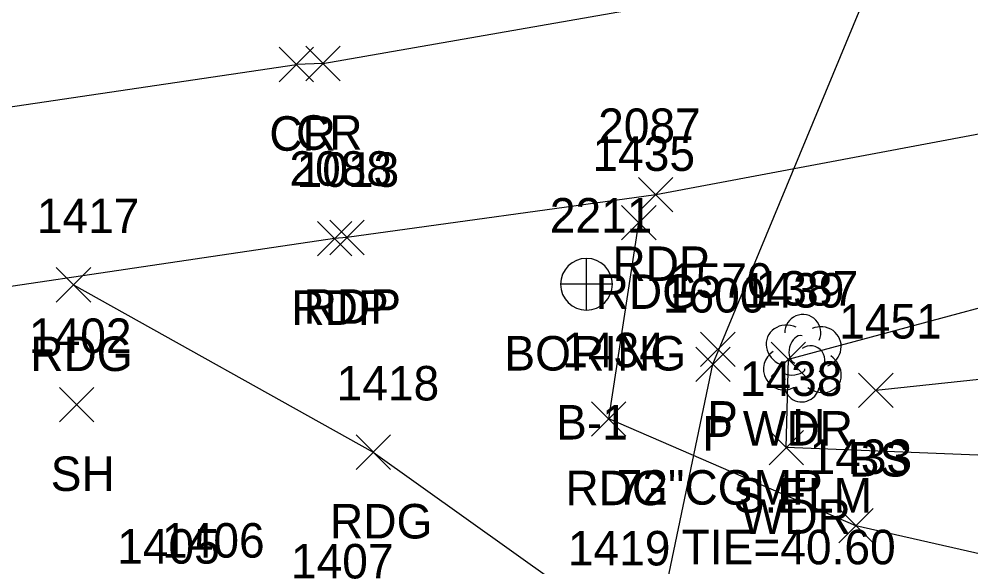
# Model space of a CAD drawing. Extents: x 1526508 to 1531550, y 369926 to 373082.
# Drawn here: x 1531020.1 to 1531075.3, y 370111.3 to 370143.1 of the extents above; entities that cross this region are included whole.
import ezdxf

# ---------------------------------------------------------------- set-up
doc = ezdxf.new("R2010")
doc.units = 0
for name, color, linetype in [('D_A', 7, 'Continuous'), ('D_C', 7, 'Continuous'), ('D_I', 7, 'Continuous'), ('D_TIC', 7, 'Continuous'), ('DCP', 7, 'Continuous'), ('G_A', 7, 'Continuous'), ('G_C', 7, 'Continuous'), ('G_I', 7, 'Continuous'), ('GA_P', 7, 'Continuous'), ('L_A', 7, 'Continuous'), ('L_C', 7, 'Continuous'), ('L_I', 7, 'Continuous'), ('L_TIC', 7, 'Continuous'), ('LAWA', 7, 'Continuous'), ('LELB', 7, 'Continuous'), ('LTD', 7, 'Continuous'), ('P_A', 7, 'Continuous'), ('P_I', 7, 'Continuous'), ('P_TIC', 7, 'Continuous'), ('PET', 7, 'Continuous'), ('PEU', 7, 'Continuous'), ('PRC', 7, 'Continuous')]:
    doc.layers.add(name, color=color, linetype=linetype)

msp = doc.modelspace()

# ---------------------------------------------------------------- linework, layer by layer
at = {"layer": 'D_TIC'}
for points in [[(1531059.668, 370122.959), (1531061.668, 370124.959)], [(1531061.668, 370122.959), (1531059.668, 370124.959)], [(1531059.382, 370122.096), (1531061.382, 370124.096)], [(1531061.382, 370122.096), (1531059.382, 370124.096)]]:
    msp.add_lwpolyline(points, dxfattribs=at)
at = {"layer": 'DCP'}
msp.add_lwpolyline([(1531055.491, 370099.698), (1531060.382, 370123.096), (1531085.607, 370183.89)], dxfattribs=at)
at = {"layer": 'GA_P'}
for p, q in [((1531053.045, 370127.735), (1531053.045, 370129.235)), ((1531053.045, 370127.735), (1531051.545, 370127.735)), ((1531054.545, 370127.735), (1531053.045, 370127.735)), ((1531053.045, 370126.235), (1531053.045, 370127.735))]:
    msp.add_line(p, q, dxfattribs=at)
for start, end in [(90, 180), (0, 90), (180, 270), (270, 0)]:
    msp.add_arc((1531053.045, 370127.735), 1.5, start, end, dxfattribs=at)
at = {"layer": 'L_TIC'}
for points in [[(1531063.755, 370122.384), (1531065.755, 370124.384)], [(1531065.755, 370122.384), (1531063.755, 370124.384)], [(1531068.826, 370120.59), (1531070.826, 370122.59)], [(1531070.826, 370120.59), (1531068.826, 370122.59)], [(1531022.481, 370119.754), (1531024.481, 370121.754)], [(1531024.481, 370119.754), (1531022.481, 370121.754)], [(1531063.636, 370117.264), (1531065.636, 370119.264)], [(1531065.636, 370117.264), (1531063.636, 370119.264)]]:
    msp.add_lwpolyline(points, dxfattribs=at)
at = {"layer": 'LAWA'}
msp.add_lwpolyline([(1531110.364, 370111.613), (1531088.81, 370117.303), (1531064.636, 370118.264), (1531064.755, 370123.384), (1531085.735, 370129.033), (1531112.085, 370135.206), (1531155.648, 370147.139), (1531210.22, 370163.604)], dxfattribs=at)
at = {"layer": 'LELB'}
msp.add_lwpolyline([(1531069.826, 370121.59), (1531102.347, 370125.05), (1531131.114, 370129.39)], dxfattribs=at)
at = {"layer": 'LTD'}
msp.add_line((1531065.548, 370123.502), (1531065.548, 370123.502), dxfattribs=at)
msp.add_line((1531065.548, 370123.502), (1531065.548, 370123.502), dxfattribs=at)
msp.add_arc((1531065.595, 370124.936), 1.047, 335.5272, 180.9563, dxfattribs=at)
for centre, major_axis, ratio, start_param, end_param in [((1531064.756, 370124.169), (1.21, -0.512), 0.895232, 1.570796, 4.712389), ((1531066.589, 370124.086), (-1.141, -0.483), 0.949671, 1.570796, 4.712389), ((1531065.339, 370123.96), (-0.208, -0.792), 0.645439, 3.141593, 6.283185), ((1531066.048, 370123.336), (-0.5, 0.667), 0.989748, 3.141593, 6.283185), ((1531064.465, 370122.794), (0.584, -1.042), 0.959034, 3.141593, 6.283185), ((1531066.548, 370122.669), (-1.09, 0.792), 0.841452, 1.570796, 4.712389), ((1531065.09, 370122.752), (-0.625, -0.083), 0.423636, 0, 3.141593), ((1531065.548, 370122.002), (0.265, 1.061), 0.942809, 1.570796, 4.712389)]:
    msp.add_ellipse(centre, major_axis=major_axis, ratio=ratio, start_param=start_param, end_param=end_param, dxfattribs=at)
at = {"layer": 'P_TIC'}
for points in [[(1531035.217, 370139.477), (1531037.217, 370141.477)], [(1531037.217, 370139.477), (1531035.217, 370141.477)], [(1531036.763, 370139.532), (1531038.763, 370141.532)], [(1531038.763, 370139.532), (1531036.763, 370141.532)], [(1531056.059, 370131.928), (1531058.059, 370133.928)], [(1531058.059, 370131.928), (1531056.059, 370133.928)], [(1531055.084, 370130.308), (1531057.084, 370132.308)], [(1531057.084, 370130.308), (1531055.084, 370132.308)], [(1531037.439, 370129.381), (1531039.439, 370131.381)], [(1531039.439, 370129.381), (1531037.439, 370131.381)], [(1531038.154, 370129.446), (1531040.154, 370131.446)], [(1531040.154, 370129.446), (1531038.154, 370131.446)], [(1531022.29, 370126.706), (1531024.29, 370128.706)], [(1531024.29, 370126.706), (1531022.29, 370128.706)], [(1531053.334, 370118.927), (1531055.334, 370120.927)], [(1531055.334, 370118.927), (1531053.334, 370120.927)], [(1531039.68, 370116.999), (1531041.68, 370118.999)], [(1531041.68, 370116.999), (1531039.68, 370118.999)], [(1531067.676, 370112.738), (1531069.676, 370114.738)], [(1531069.676, 370112.738), (1531067.676, 370114.738)]]:
    msp.add_lwpolyline(points, dxfattribs=at)
at = {"layer": 'PET'}
for points in [[(1531538.536, 370286.021), (1531506.284, 370274.482), (1531462.757, 370259.55), (1531429.61, 370248.076), (1531393.109, 370234.633), (1531350.619, 370219.916), (1531310.671, 370205.954), (1531271.31, 370192.301), (1531228.453, 370178.009), (1531188.403, 370165.276), (1531155.956, 370155.782), (1531116.2, 370145.37), (1531081.97, 370137.606), (1531057.059, 370132.928), (1531039.154, 370130.446)], [(1531038.439, 370130.381), (1531006.599, 370125.669), (1530965.469, 370120.559), (1530935.626, 370115.811), (1530906.909, 370106.244), (1530877.457, 370092.886), (1530855.502, 370080.74), (1530824.981, 370062.428), (1530800.479, 370048.152), (1530769.959, 370030.14), (1530741.096, 370012.789), (1530710.763, 369994.526), (1530684.029, 369978.659), (1530669.597, 369970.091)], [(1531039.154, 370130.446), (1531038.439, 370130.381)]]:
    msp.add_lwpolyline(points, dxfattribs=at)
at = {"layer": 'PEU'}
for points in [[(1531132.305, 370060.9), (1531128.071, 370080.387), (1531123.919, 370092.189), (1531113.282, 370102.83), (1531106.52, 370106.994), (1531097.458, 370108.784), (1531079.316, 370111.323), (1531068.676, 370113.738), (1531054.334, 370119.927), (1531056.084, 370131.308)], [(1531023.29, 370127.706), (1531040.68, 370117.999), (1531054.099, 370108.435), (1531069.601, 370103.939), (1531084.917, 370101.163), (1531104.196, 370096.573), (1531116.34, 370088.254), (1531119.549, 370080.003), (1531124.942, 370058.759)]]:
    msp.add_lwpolyline(points, dxfattribs=at)
at = {"layer": 'PRC'}
for points in [[(1531037.763, 370140.532), (1531081.386, 370148.168), (1531130.613, 370160.035), (1531176.301, 370172.813), (1531216.718, 370185.489), (1531265.367, 370201.607), (1531315.135, 370219.142), (1531364.467, 370236.544), (1531403.005, 370250.24), (1531441.257, 370263.858), (1531484.777, 370279.08), (1531519.825, 370291.48), (1531535.781, 370296.891)], [(1530664.429, 369978.533), (1530688.651, 369992.904), (1530715.759, 370008.787), (1530744.405, 370025.809), (1530774.386, 370044.325), (1530799.133, 370059.29), (1530828.468, 370076.59), (1530863.719, 370096.733), (1530899.644, 370113.889), (1530935.777, 370125.965), (1530974.766, 370132.269), (1531009.674, 370136.559), (1531036.217, 370140.477)], [(1531037.763, 370140.532), (1531036.217, 370140.477)]]:
    msp.add_lwpolyline(points, dxfattribs=at)

# ---------------------------------------------------------------- texts
at = {"layer": 'D_A'}
for p in [(1531060.045, 370118.959), (1531059.76, 370118.096)]:
    msp.add_text('P', height=2, dxfattribs=at).set_placement(p)
at = {"layer": 'D_C'}
msp.add_text('72"CGMP', height=2, dxfattribs=at).set_placement((1531054.801, 370114.959))
at = {"layer": 'D_I'}
for s, p in [('1570', (1531057.888, 370126.959)), ('1600', (1531057.477, 370126.096))]:
    msp.add_text(s, height=2, dxfattribs=at).set_placement(p)
at = {"layer": 'G_A'}
msp.add_text('BORING', height=2, dxfattribs=at).set_placement((1531048.282, 370122.735))
at = {"layer": 'G_C'}
msp.add_text('B-1', height=2, dxfattribs=at).set_placement((1531051.282, 370118.735))
at = {"layer": 'G_I'}
msp.add_text('2211', height=2, dxfattribs=at).set_placement((1531050.919, 370130.735))
at = {"layer": 'L_A'}
for s, p in [('WDR', (1531062.117, 370118.384)), ('H', (1531064.981, 370118.502)), ('BS', (1531068.267, 370116.59)), ('SH', (1531021.969, 370115.754)), ('WDR', (1531061.999, 370113.264))]:
    msp.add_text(s, height=2, dxfattribs=at).set_placement(p)
at = {"layer": 'L_C'}
for s, p in [('S.ELM', (1531061.579, 370114.502)), ('TIE=40.60', (1531058.564, 370111.502))]:
    msp.add_text(s, height=2, dxfattribs=at).set_placement(p)
at = {"layer": 'L_I'}
for s, p in [('1387', (1531062.855, 370126.502)), ('1439', (1531062.054, 370126.384)), ('1451', (1531067.7, 370124.59)), ('1402', (1531020.709, 370123.754)), ('1438', (1531061.943, 370121.264)), ('1406', (1531028.429, 370111.889)), ('1405', (1531025.826, 370111.539)), ('1407', (1531035.904, 370110.681))]:
    msp.add_text(s, height=2, dxfattribs=at).set_placement(p)
at = {"layer": 'P_A'}
for s, p in [('CR', (1531034.65, 370135.477)), ('CR', (1531036.196, 370135.532)), ('RDP', (1531054.548, 370127.928)), ('RDG', (1531053.572, 370126.308)), ('RDP', (1531036.642, 370125.446)), ('RDP', (1531035.928, 370125.381)), ('RDG', (1531020.779, 370122.706)), ('RDG', (1531051.823, 370114.927)), ('RDG', (1531038.168, 370112.999))]:
    msp.add_text(s, height=2, dxfattribs=at).set_placement(p)
at = {"layer": 'P_I'}
for s, p in [('2087', (1531053.721, 370135.928)), ('1435', (1531053.391, 370134.308)), ('2088', (1531035.815, 370133.446)), ('1013', (1531036.235, 370133.381)), ('1417', (1531021.165, 370130.706)), ('1434', (1531051.642, 370122.927)), ('1418', (1531038.554, 370120.999)), ('1433', (1531065.983, 370116.738)), ('1419', (1531051.965, 370111.435))]:
    msp.add_text(s, height=2, dxfattribs=at).set_placement(p)

doc.saveas('drawing.dxf')
